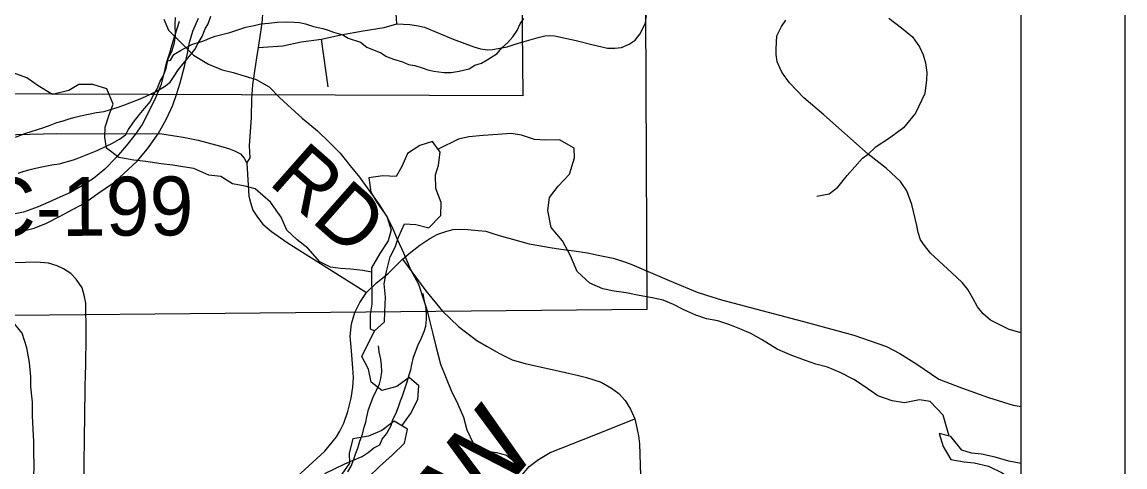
# Model space of a CAD drawing. Extents: x -21.1 to 50.3, y 0 to 22.1.
# Drawn here: x 7.937 to 9, y 14.756 to 15.185 of the extents above; entities that cross this region are included whole.
import ezdxf

# ---------------------------------------------------------------- set-up
doc = ezdxf.new("R2010")
doc.units = 0
for name, color, linetype in [('GM_X_County', 7, 'Continuous'), ('GM_X_County_Road', 7, 'Continuous'), ('GM_X_County_Road_Text', 7, 'Continuous'), ('GM_X_Major_River', 7, 'Continuous'), ('GM_X_Minor_Lake', 7, 'Continuous'), ('GM_X_Minor_River', 7, 'Continuous'), ('GM_X_Minor_River_Text', 7, 'Continuous'), ('GM_X_Section', 7, 'Continuous'), ('GM_X_State_Route', 7, 'Continuous'), ('GM_X_Township_Road', 7, 'Continuous'), ('SH_Cut_Line', 7, 'Continuous'), ('SH_Data', 7, 'Continuous')]:
    doc.layers.add(name, color=color, linetype=linetype)

msp = doc.modelspace()

# ---------------------------------------------------------------- linework, layer by layer
at = {"layer": 'GM_X_County'}
msp.add_lwpolyline([(8.9, 14.7464), (8.9, 20.9), (2.1, 20.9), (2.1, 14.1), (8.8932, 14.1)], dxfattribs=at)
at = {"layer": 'GM_X_County_Road'}
for points in [[(7.853, 15.0746), (7.9701, 15.0775), (8.0713, 15.0771), (8.092, 15.0741), (8.1065, 15.0711), (8.128, 15.0653), (8.1367, 15.0627), (8.1415, 15.0608), (8.1471, 15.058), (8.1507, 15.0537), (8.1533, 15.0488), (8.1552, 15.0172), (8.1568, 15.0111), (8.1592, 15.0035), (8.1635, 14.9969), (8.1687, 14.99), (8.177, 14.9829), (8.1923, 14.9724), (8.2686, 14.9241)], [(8.182, 14.7285), (8.2285, 14.7714), (8.2398, 14.7852), (8.2431, 14.7905), (8.247, 14.7981), (8.2507, 14.8096), (8.2539, 14.8225), (8.2555, 14.8331), (8.2562, 14.8423), (8.2556, 14.8513), (8.2543, 14.8681), (8.253, 14.882), (8.2541, 14.8939), (8.2573, 14.9048), (8.2622, 14.9147), (8.2686, 14.9241), (8.2785, 14.9334), (8.2893, 14.9421), (8.3034, 14.9563), (8.3115, 14.9632), (8.3202, 14.9699), (8.3297, 14.9763), (8.3376, 14.9806), (8.3452, 14.9831), (8.352, 14.9849), (8.3582, 14.9854), (8.3665, 14.9851), (8.3763, 14.9841), (8.3837, 14.9833), (8.3926, 14.9806), (8.4012, 14.9779), (8.4095, 14.9758), (8.4255, 14.9713), (8.435, 14.9694), (8.4459, 14.9677), (8.4562, 14.9659), (8.4686, 14.9644), (8.4817, 14.9625), (8.4922, 14.9603), (8.5067, 14.9573), (8.5165, 14.9542), (8.5229, 14.952), (8.5313, 14.9483), (8.5604, 14.9357), (8.5875, 14.9247), (8.5965, 14.9218), (8.611, 14.9173), (8.6948, 14.895), (8.7386, 14.883), (8.77, 14.8722), (8.7829, 14.8654), (8.7992, 14.855), (8.8204, 14.8406), (8.8425, 14.8322), (8.8685, 14.8229), (8.8922, 14.8155), (8.9, 14.8142)]]:
    msp.add_lwpolyline(points, dxfattribs=at)
at = {"layer": 'GM_X_Major_River'}
for points in [[(8.0881, 15.1856), (8.0817, 15.1652), (8.0789, 15.155), (8.0757, 15.1452), (8.0729, 15.1342), (8.0704, 15.124), (8.0653, 15.1119), (8.059, 15.0994), (8.0524, 15.0863), (8.0458, 15.0765), (8.0369, 15.0656), (8.0276, 15.0547), (8.0164, 15.0431), (8.0056, 15.0342), (7.9933, 15.0264), (7.9834, 15.0208), (7.973, 15.016), (7.9623, 15.0113), (7.952, 15.0069), (7.9379, 15.0018), (7.9268, 14.9993)], [(7.9342, 14.9828), (7.9483, 14.9864), (7.9601, 14.9912), (7.9735, 14.9978), (7.9858, 15.0045), (7.9969, 15.0104), (8.0095, 15.0197), (8.0249, 15.0301), (8.0345, 15.0387), (8.0476, 15.051), (8.0577, 15.0626), (8.0678, 15.0773), (8.076, 15.0916), (8.0819, 15.1048), (8.0859, 15.1161), (8.0891, 15.1263), (8.0931, 15.1422), (8.096, 15.1547), (8.098, 15.1653), (8.1012, 15.1763), (8.1067, 15.1888)]]:
    msp.add_lwpolyline(points, dxfattribs=at)
at = {"layer": 'GM_X_Minor_Lake'}
for points in [[(8.2763, 14.8873), (8.286, 14.8958), (8.2863, 14.9056), (8.287, 14.9197), (8.2857, 14.9326), (8.2879, 14.9444), (8.2916, 14.9585), (8.2964, 14.968), (8.2997, 14.9776), (8.3053, 14.9905), (8.3163, 14.9899), (8.3289, 14.9866), (8.3405, 14.9985), (8.3408, 15.011), (8.3357, 15.0246), (8.3352, 15.0376), (8.3382, 15.0471), (8.3396, 15.0596), (8.3323, 15.0698), (8.3202, 15.0659), (8.3081, 15.0582), (8.3029, 15.0456), (8.2973, 15.0361), (8.2844, 15.0367), (8.2708, 15.0347), (8.2728, 15.021), (8.2789, 15.0108), (8.2882, 14.9976), (8.2925, 14.9847), (8.2895, 14.9741), (8.2817, 14.9618), (8.2734, 14.9481), (8.2735, 14.9352), (8.274, 14.9253), (8.2737, 14.9131), (8.2723, 14.9032), (8.2724, 14.8892)], [(8.2724, 14.8892), (8.2763, 14.8873)], [(8.2707, 14.7463), (8.2812, 14.7566), (8.2933, 14.7674), (8.3053, 14.7789), (8.3082, 14.7926), (8.2953, 14.8001), (8.2836, 14.7912), (8.2707, 14.7858), (8.2556, 14.783), (8.2519, 14.7693), (8.2524, 14.7598), (8.2449, 14.7491)]]:
    msp.add_lwpolyline(points, dxfattribs=at)
at = {"layer": 'GM_X_Minor_River'}
for points in [[(7.9302, 15.0741), (7.9401, 15.0779), (7.9454, 15.0795), (7.9575, 15.0834), (7.9636, 15.0857), (7.9701, 15.088), (7.9761, 15.0899), (7.9811, 15.0915), (7.9864, 15.093), (7.9929, 15.0946), (8.0005, 15.0961), (8.0085, 15.0977), (8.0157, 15.0989), (8.0294, 15.1028), (8.0347, 15.1047), (8.0522, 15.1116), (8.0616, 15.1162), (8.0666, 15.1185), (8.0738, 15.1228), (8.0795, 15.127), (8.0825, 15.1319), (8.0874, 15.1392), (8.0931, 15.1464), (8.098, 15.1521), (8.1033, 15.1586), (8.1063, 15.1647), (8.1101, 15.1712), (8.1131, 15.1784), (8.1161, 15.1834), (8.1187, 15.1906)], [(7.9329, 15.0394), (7.9378, 15.041), (7.9431, 15.0425), (7.9496, 15.0441), (7.9572, 15.0456), (7.9652, 15.0472), (7.9724, 15.0484), (7.9861, 15.0522), (7.9914, 15.0542), (8.0089, 15.0611), (8.0184, 15.0657), (8.0233, 15.068), (8.0305, 15.0722), (8.0362, 15.0764), (8.0392, 15.0814), (8.0441, 15.0886), (8.0498, 15.0959), (8.0547, 15.1016), (8.06, 15.1081), (8.063, 15.1142), (8.0668, 15.1207), (8.0698, 15.1279), (8.0728, 15.1329), (8.0754, 15.1401), (8.0776, 15.1496), (8.0814, 15.1576), (8.0836, 15.1652), (8.0844, 15.1724), (8.0843, 15.1831), (8.0847, 15.1895)], [(8.0734, 15.1879), (8.0779, 15.1773), (8.0892, 15.1658), (8.102, 15.1532), (8.1164, 15.1444), (8.1296, 15.139), (8.1402, 15.1363), (8.1508, 15.1332), (8.1622, 15.1297), (8.1747, 15.1224), (8.1848, 15.1121), (8.1965, 15.1018), (8.2067, 15.0922), (8.2214, 15.08), (8.2331, 15.0689), (8.2433, 15.0586), (8.2531, 15.0464), (8.2621, 15.0354), (8.2711, 15.0228), (8.2809, 15.0091), (8.2888, 14.9961), (8.2941, 14.9855), (8.2982, 14.9756), (8.3045, 14.9626), (8.3116, 14.9459), (8.3187, 14.9322), (8.324, 14.9166), (8.3273, 14.9067), (8.3295, 14.8972), (8.3328, 14.8843), (8.3354, 14.8725), (8.3402, 14.8551), (8.3455, 14.8417), (8.3503, 14.8296), (8.3567, 14.8166), (8.3623, 14.8041), (8.3656, 14.7919), (8.3716, 14.779), (8.3833, 14.7717), (8.3939, 14.7701), (8.4038, 14.7674), (8.4181, 14.7559)], [(8.0772, 15.1475), (8.0796, 15.1481), (8.0829, 15.1538), (8.0894, 15.1577), (8.0943, 15.16), (8.1008, 15.1638), (8.1076, 15.1657), (8.1126, 15.1673), (8.1175, 15.1696), (8.1228, 15.1715), (8.1369, 15.175), (8.1475, 15.1785), (8.1525, 15.18), (8.1604, 15.1816), (8.1669, 15.1832), (8.1745, 15.184), (8.1825, 15.1848), (8.1916, 15.1852), (8.1989, 15.1849), (8.2042, 15.1845), (8.2099, 15.1834), (8.2175, 15.1808), (8.2267, 15.1789), (8.2316, 15.1771), (8.237, 15.1752), (8.2458, 15.1726), (8.2511, 15.1696), (8.2629, 15.1655), (8.269, 15.1609), (8.2824, 15.1553), (8.2881, 15.1519), (8.2946, 15.1493), (8.3034, 15.1467), (8.3091, 15.1441), (8.3152, 15.143), (8.3224, 15.1407), (8.3278, 15.1388), (8.3335, 15.1377), (8.3434, 15.1363), (8.3503, 15.1363), (8.3579, 15.1375), (8.3677, 15.1398), (8.3731, 15.1433), (8.3795, 15.1452), (8.3852, 15.1487), (8.3947, 15.1548), (8.3992, 15.1601), (8.4045, 15.1651), (8.4098, 15.1708), (8.414, 15.1769), (8.417, 15.1834), (8.4204, 15.1884)], [(8.2735, 14.9439), (8.2651, 14.9453), (8.2537, 14.9467), (8.2435, 14.9474), (8.234, 14.9488), (8.2237, 14.9537), (8.2122, 14.9669), (8.2018, 14.9751), (8.1919, 14.9842), (8.1865, 14.997), (8.1761, 15.0114), (8.1612, 15.0241), (8.1517, 15.0267), (8.1395, 15.0289), (8.1281, 15.036), (8.1167, 15.0374), (8.1022, 15.0437), (8.0915, 15.0455), (8.082, 15.047), (8.0707, 15.0484), (8.0558, 15.0505), (8.0444, 15.0519), (8.03, 15.0544), (8.0181, 15.0635), (8.0165, 15.0741), (8.0168, 15.0836), (8.0205, 15.0954), (8.0246, 15.1057), (8.0184, 15.1205), (8.0047, 15.1249), (7.9914, 15.1248), (7.9816, 15.119), (7.9661, 15.115), (7.952, 15.1236), (7.9413, 15.1311), (7.9279, 15.1359)], [(8.8304, 14.7858), (8.8246, 14.8058), (8.8123, 14.819), (8.802, 14.8208), (8.7876, 14.818), (8.7755, 14.8198), (8.7618, 14.8246), (8.7488, 14.8336), (8.7385, 14.8403), (8.7255, 14.8471), (8.7133, 14.8523), (8.7019, 14.8552), (8.6909, 14.8589), (8.6772, 14.8641), (8.6646, 14.8697), (8.6497, 14.879), (8.6394, 14.8846), (8.6288, 14.8891), (8.6189, 14.8932), (8.6074, 14.8969), (8.5964, 14.899), (8.5862, 14.9024), (8.5747, 14.9076), (8.5648, 14.9128), (8.5549, 14.9169), (8.5443, 14.9191), (8.5317, 14.9212), (8.5192, 14.9238), (8.5074, 14.9256), (8.4967, 14.9277), (8.4842, 14.9333), (8.4719, 14.9446), (8.4653, 14.9597), (8.4576, 14.9741), (8.4469, 14.9869), (8.4437, 15.0032), (8.4451, 15.0158), (8.4534, 15.0269), (8.4643, 15.0384), (8.4694, 15.054), (8.469, 15.0635), (8.4549, 15.0714), (8.4412, 15.0712), (8.4306, 15.0719), (8.418, 15.0759), (8.4081, 15.0774), (8.3952, 15.0765), (8.3812, 15.0756), (8.3675, 15.0743), (8.3573, 15.072), (8.3377, 15.0623)], [(7.9478, 14.7452), (7.9484, 14.7581), (7.9479, 14.7699), (7.9478, 14.7805), (7.9473, 14.7923), (7.9468, 14.8056), (7.9467, 14.8185), (7.9451, 14.8333), (7.945, 14.8428), (7.9437, 14.8568), (7.9413, 14.8709), (7.9366, 14.8849), (7.9267, 14.8973), (7.9167, 14.9075), (7.903, 14.9153), (7.8931, 14.9206), (7.8828, 14.9269)], [(8.2285, 14.7498), (8.2479, 14.759), (8.2551, 14.7621), (8.2646, 14.766), (8.2703, 14.7698), (8.2759, 14.7744), (8.2816, 14.7775), (8.2839, 14.7828), (8.2881, 14.7878), (8.2926, 14.7961), (8.2941, 14.8018), (8.2971, 14.8072), (8.2997, 14.814), (8.3016, 14.8197), (8.3035, 14.8247), (8.3057, 14.8315), (8.3079, 14.838), (8.3098, 14.8449), (8.3113, 14.8498), (8.3124, 14.8547), (8.3139, 14.862), (8.3184, 14.8738), (8.3218, 14.8806), (8.3244, 14.8867), (8.3259, 14.8917), (8.3266, 14.8981), (8.3266, 14.905), (8.3258, 14.9107), (8.3242, 14.9175), (8.3235, 14.9232)], [(8.3027, 14.7958), (8.3111, 14.8071), (8.3182, 14.8212), (8.3192, 14.8341), (8.3097, 14.8424), (8.298, 14.8335), (8.2836, 14.8296), (8.2733, 14.8379), (8.2705, 14.8504), (8.2643, 14.8625), (8.2763, 14.8873)], [(8.2508, 14.7513), (8.2538, 14.7567), (8.2564, 14.7635), (8.2583, 14.7692), (8.2602, 14.7742), (8.2624, 14.781), (8.2647, 14.7875), (8.2665, 14.7943), (8.268, 14.7993), (8.2691, 14.8042), (8.2706, 14.8115), (8.2751, 14.8233), (8.2785, 14.8301), (8.2811, 14.8362), (8.2826, 14.8412), (8.2834, 14.8476), (8.2833, 14.8544), (8.2825, 14.8601), (8.281, 14.867), (8.2802, 14.8727)], [(8.8522, 14.7692), (8.8427, 14.7722), (8.832, 14.7854), (8.8209, 14.7883), (8.8248, 14.7758), (8.8322, 14.7633), (8.8451, 14.7608), (8.8546, 14.7601), (8.8683, 14.7568), (8.8816, 14.7505), (8.8927, 14.743), (8.9, 14.7428)], [(8.9, 14.7595), (8.888, 14.7616), (8.875, 14.7656), (8.8617, 14.7685), (8.8522, 14.7692)]]:
    msp.add_lwpolyline(points, dxfattribs=at)
at = {"layer": 'GM_X_Section'}
for points in [[(7.4213, 16.1221), (8.4094, 16.1114), (8.4195, 15.1137), (7.4245, 15.1173)], [(7.5252, 15.9214), (7.573, 15.9211), (8.5344, 15.9142), (8.5389, 14.908), (7.5222, 14.8982)]]:
    msp.add_lwpolyline(points, close=True, dxfattribs=at)
at = {"layer": 'GM_X_State_Route'}
msp.add_lwpolyline([(8.9, 14.1), (8.9, 17.8422), (8.2576, 17.8312), (7.8664, 17.8239), (7.5837, 17.8195), (6.9093, 17.8143), (6.7, 17.8119), (6.6641, 17.812), (6.522, 17.8104), (6.5205, 17.7208), (6.5201, 17.6965), (6.5222, 16.8567), (6.5232, 16.4681), (6.5212, 16.2452), (6.5198, 16.0826), (6.5159, 15.4923), (6.5146, 15.3031), (6.514, 15.0936), (6.5146, 15.0349), (6.5142, 14.9441), (6.5128, 14.6032)], dxfattribs=at)
at = {"layer": 'GM_X_Township_Road'}
msp.add_line((8.2319, 15.1224), (8.2253, 15.1686), dxfattribs=at)
for points in [[(8.2981, 15.1832), (8.2951, 15.229), (8.291, 15.264), (8.2896, 15.2758), (8.2845, 15.2882), (8.2781, 15.3064), (8.2731, 15.3192), (8.2707, 15.3301), (8.2691, 15.3393), (8.2681, 15.3502), (8.2682, 15.3596), (8.2691, 15.372), (8.2696, 15.3841), (8.2689, 15.3924)], [(8.1533, 15.0488), (8.1566, 15.054), (8.1559, 15.0658), (8.1578, 15.093), (8.158, 15.111), (8.1592, 15.1245), (8.1609, 15.1376), (8.163, 15.1504), (8.1647, 15.1605), (8.1681, 15.1839), (8.17, 15.2098)], [(8.5324, 15.1732), (8.5353, 15.1788), (8.5376, 15.1842), (8.5388, 15.1913)], [(8.9, 14.8854), (8.8986, 14.8858), (8.8885, 14.8885), (8.8703, 14.8974), (8.8632, 14.9037), (8.8577, 14.9104), (8.8535, 14.9182), (8.8485, 14.927), (8.8431, 14.934), (8.8331, 14.9433), (8.8125, 14.9621), (8.8068, 14.9696), (8.8029, 14.975), (8.8007, 14.982), (8.7992, 14.9889), (8.7946, 15.0092), (8.7897, 15.0221), (8.7835, 15.0311), (8.77, 15.0437), (8.7524, 15.0576), (8.7096, 15.0954), (8.6904, 15.1119), (8.6766, 15.1264), (8.6691, 15.1366), (8.6647, 15.1468), (8.6638, 15.1536), (8.6637, 15.1592), (8.6645, 15.1718), (8.669, 15.1807), (8.673, 15.1868)], [(8.7724, 15.1887), (8.7847, 15.1795), (8.7952, 15.1706), (8.802, 15.161), (8.8055, 15.1533), (8.8078, 15.1456), (8.8089, 15.1364), (8.8088, 15.1293), (8.8069, 15.1161), (8.798, 15.0973), (8.7866, 15.0831), (8.7731, 15.0729), (8.7593, 15.0639), (8.7524, 15.0576)], [(8.1647, 15.1605), (8.1881, 15.1622), (8.2056, 15.166), (8.2253, 15.1686), (8.2438, 15.1726), (8.2655, 15.1766), (8.2859, 15.1799), (8.2981, 15.1832), (8.3106, 15.1825), (8.3169, 15.1816), (8.3246, 15.1802), (8.3523, 15.1684), (8.3722, 15.1611), (8.3787, 15.1591), (8.3854, 15.1582), (8.3903, 15.1586), (8.3958, 15.1596), (8.4043, 15.1612), (8.4119, 15.1638), (8.4207, 15.1662), (8.4342, 15.1702), (8.4408, 15.1717), (8.4453, 15.1721), (8.4501, 15.1718), (8.4708, 15.1673), (8.486, 15.1634), (8.5012, 15.1598), (8.5083, 15.1598), (8.5147, 15.1605), (8.522, 15.1636), (8.5277, 15.1676), (8.5324, 15.1732)], [(8.703, 15.0171), (8.7147, 15.0195), (8.7231, 15.0258), (8.7323, 15.037), (8.7471, 15.0537), (8.7524, 15.0576)], [(7.9979, 14.8481), (7.998, 14.851), (7.9984, 14.8849), (7.9982, 14.9138), (7.9965, 14.9218), (7.9946, 14.9287), (7.9889, 14.937), (7.9837, 14.9424), (7.9766, 14.9472), (7.9705, 14.95), (7.9622, 14.9524), (7.9506, 14.9535), (7.8558, 14.9506)], [(8.3034, 14.9563), (8.326, 14.9259), (8.342, 14.9061), (8.3574, 14.8913), (8.3752, 14.878), (8.385, 14.8721), (8.3968, 14.8655), (8.4093, 14.8594), (8.4217, 14.8559), (8.4606, 14.8471), (8.4719, 14.8446), (8.4809, 14.8422), (8.4949, 14.8378), (8.5048, 14.8319), (8.5119, 14.8268), (8.5182, 14.8201), (8.5232, 14.8118), (8.5274, 14.8025), (8.5295, 14.7939), (8.531, 14.786), (8.532, 14.7782), (8.5334, 14.7279)], [(7.9951, 14.6099), (7.9958, 14.7125), (7.9975, 14.83), (7.9979, 14.8481)], [(8.4125, 14.3627), (8.4105, 14.3669), (8.4092, 14.3778), (8.409, 14.4722), (8.4079, 14.5458), (8.4079, 14.6385), (8.4076, 14.7007), (8.4088, 14.72), (8.4107, 14.732), (8.4144, 14.7401), (8.4191, 14.7489), (8.4257, 14.7565), (8.4345, 14.7632), (8.4459, 14.7698), (8.4881, 14.7867), (8.5274, 14.8025)]]:
    msp.add_lwpolyline(points, dxfattribs=at)
at = {"layer": 'SH_Cut_Line'}
msp.add_lwpolyline([(6.5099, 14.1), (8.9, 14.1), (8.9, 20.9), (6.5295, 20.9), (6.5298, 20.3986), (6.5227, 19.3467), (6.5225, 18.9778), (6.5223, 18.3569), (6.522, 17.8104), (6.5205, 17.7208), (6.5201, 17.6965), (6.5222, 16.8567), (6.5232, 16.4681), (6.5212, 16.2452), (6.5198, 16.0826), (6.5159, 15.4923), (6.5146, 15.3031), (6.514, 15.0936), (6.5146, 15.0349), (6.5142, 14.9441), (6.5128, 14.6032), (6.513, 14.4147), (6.5111, 14.2942), (6.5113, 14.2435)], close=True, dxfattribs=at)
at = {"layer": 'SH_Data'}
msp.add_line((9, 21), (9, 14), dxfattribs=at)

# ---------------------------------------------------------------- texts
at = {"layer": 'GM_X_County_Road_Text'}
for s, rotation, p in [('RD', 318.5757, (8.173, 15.0297)), ('C-199', 0.2695, (7.895, 14.9784))]:
    msp.add_text(s, height=0.05682, rotation=rotation, dxfattribs=at).set_placement(p)
at = {"layer": 'GM_X_Minor_River_Text'}
msp.add_text('Yellow', height=0.09475, rotation=49.8757, dxfattribs=at).set_placement((8.1944, 14.487))

doc.saveas('drawing.dxf')
